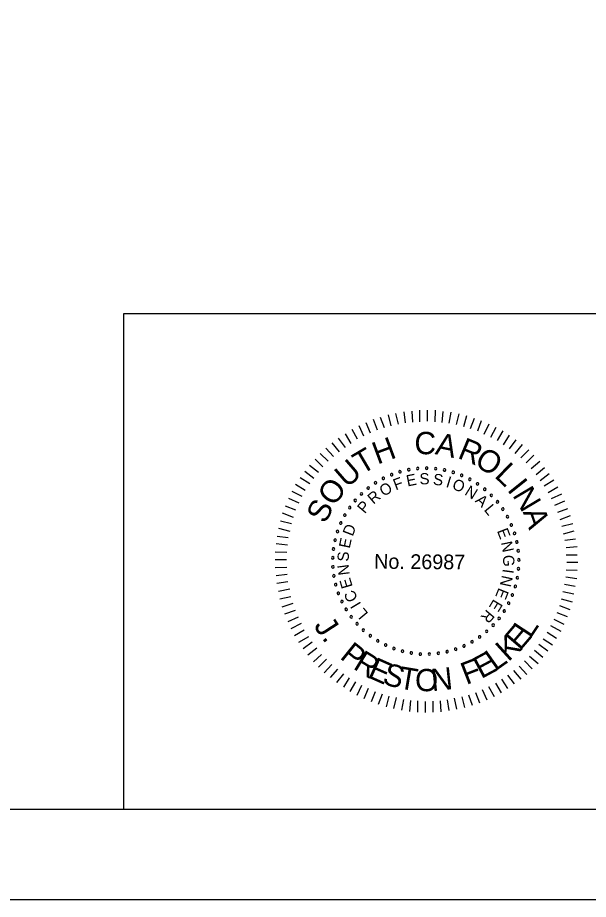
# Model space of a CAD drawing. Extents: x -305 to -161, y -187 to -99.
# Drawn here: x -216.99 to -204.34, y -187.49 to -167.93 of the extents above; entities that cross this region are included whole.
import ezdxf

# ---------------------------------------------------------------- set-up
doc = ezdxf.new("R2010")
doc.units = 0
for name, color, linetype in [('BR_BORDER LINES', 7, 'Continuous'), ('BR_TEXT', 7, 'Continuous'), ('Level 31', 7, 'Continuous')]:
    doc.layers.add(name, color=color, linetype=linetype)

msp = doc.modelspace()

# ---------------------------------------------------------------- linework, layer by layer
at = {"layer": 'BR_BORDER LINES'}
for p, q in [((-214.64, -174.489), (-193.18, -174.489)), ((-214.64, -185.489), (-214.64, -174.489)), ((-297.843, -185.489), (-163.178, -185.489))]:
    msp.add_line(p, q, dxfattribs=at)
at = {"layer": 'BR_TEXT'}
for p, q in [((-208.077, -176.892), (-208.075, -176.634)), ((-207.909, -176.883), (-207.907, -176.636)), ((-207.741, -176.895), (-207.732, -176.637)), ((-208.861, -177.026), (-208.949, -176.795)), ((-208.717, -176.986), (-208.77, -176.742)), ((-208.552, -176.946), (-208.608, -176.709)), ((-208.394, -176.917), (-208.429, -176.673)), ((-208.236, -176.901), (-208.251, -176.657)), ((-207.58, -176.906), (-207.561, -176.663)), ((-207.426, -176.925), (-207.382, -176.681)), ((-207.265, -176.957), (-207.208, -176.721)), ((-207.1, -176.999), (-207.036, -176.756)), ((-206.953, -177.042), (-206.865, -176.813)), ((-209.323, -177.211), (-209.427, -176.987)), ((-209.175, -177.144), (-209.269, -176.92)), ((-209.02, -177.076), (-209.103, -176.842)), ((-206.795, -177.095), (-206.708, -176.862)), ((-206.652, -177.165), (-206.54, -176.942)), ((-206.508, -177.234), (-206.383, -177.012)), ((-209.602, -177.377), (-209.724, -177.16)), ((-209.461, -177.282), (-209.582, -177.065)), ((-206.358, -177.308), (-206.229, -177.093)), ((-206.225, -177.405), (-206.089, -177.19)), ((-209.861, -177.564), (-210.021, -177.363)), ((-209.726, -177.462), (-209.883, -177.258)), ((-206.091, -177.492), (-205.946, -177.291)), ((-205.962, -177.596), (-205.799, -177.398)), ((-210.11, -177.771), (-210.287, -177.594)), ((-209.993, -177.662), (-210.159, -177.482)), ((-205.836, -177.696), (-205.663, -177.519)), ((-210.228, -177.894), (-210.402, -177.724)), ((-205.723, -177.807), (-205.55, -177.634)), ((-205.611, -177.932), (-205.421, -177.765)), ((-210.432, -178.153), (-210.63, -177.993)), ((-210.328, -178.02), (-210.526, -177.864)), ((-205.502, -178.06), (-205.316, -177.907)), ((-210.519, -178.269), (-210.735, -178.137)), ((-205.407, -178.194), (-205.21, -178.038)), ((-205.319, -178.312), (-205.109, -178.183)), ((-210.617, -178.416), (-210.832, -178.287)), ((-205.231, -178.46), (-205.017, -178.335)), ((-210.686, -178.552), (-210.912, -178.441)), ((-205.16, -178.598), (-204.929, -178.49)), ((-210.826, -178.853), (-211.059, -178.766)), ((-210.756, -178.699), (-210.985, -178.598)), ((-205.089, -178.746), (-204.862, -178.648)), ((-210.876, -179.014), (-211.122, -178.923)), ((-205.022, -178.901), (-204.795, -178.817)), ((-204.968, -179.063), (-204.738, -178.976)), ((-210.925, -179.158), (-211.168, -179.098)), ((-204.928, -179.207), (-204.688, -179.151)), ((-210.954, -179.326), (-211.204, -179.262)), ((-204.895, -179.376), (-204.654, -179.316)), ((-210.996, -179.47), (-211.24, -179.437)), ((-204.862, -179.52), (-204.625, -179.491)), ((-211.015, -179.634), (-211.261, -179.605)), ((-204.836, -179.685), (-204.592, -179.66)), ((-211.034, -179.957), (-211.285, -179.955)), ((-211.026, -179.792), (-211.284, -179.79)), ((-204.831, -179.843), (-204.59, -179.845)), ((-211.029, -180.129), (-211.286, -180.133)), ((-204.822, -180.008), (-204.578, -180.01)), ((-211.02, -180.283), (-211.267, -180.312)), ((-204.841, -180.334), (-204.598, -180.367)), ((-204.833, -180.18), (-204.593, -180.189)), ((-211.004, -180.448), (-211.248, -180.484)), ((-204.87, -180.499), (-204.634, -180.538)), ((-210.964, -180.606), (-211.215, -180.659)), ((-204.906, -180.656), (-204.666, -180.713)), ((-210.938, -180.775), (-211.182, -180.831)), ((-210.891, -180.923), (-211.139, -181.006)), ((-204.942, -180.824), (-204.702, -180.885)), ((-210.845, -181.077), (-211.079, -181.161)), ((-205.04, -181.125), (-204.814, -181.213)), ((-204.984, -180.971), (-204.755, -181.059)), ((-210.777, -181.226), (-211.008, -181.334)), ((-205.11, -181.272), (-204.884, -181.384)), ((-210.71, -181.37), (-210.937, -181.489)), ((-210.642, -181.519), (-210.859, -181.644)), ((-205.183, -181.416), (-204.954, -181.538)), ((-210.547, -181.667), (-210.765, -181.792)), ((-205.347, -181.71), (-205.139, -181.839)), ((-205.257, -181.563), (-205.045, -181.692)), ((-210.462, -181.784), (-210.663, -181.93)), ((-210.361, -181.919), (-210.561, -182.075)), ((-205.437, -181.826), (-205.243, -181.975)), ((-210.262, -182.054), (-210.439, -182.217)), ((-205.645, -182.092), (-205.458, -182.258)), ((-205.535, -181.959), (-205.351, -182.118)), ((-210.146, -182.158), (-210.326, -182.338)), ((-210.031, -182.279), (-210.2, -182.463)), ((-205.874, -182.313), (-205.704, -182.5)), ((-205.76, -182.194), (-205.589, -182.377)), ((-209.901, -182.383), (-210.064, -182.57)), ((-209.768, -182.487), (-209.928, -182.678)), ((-206.002, -182.415), (-205.842, -182.605)), ((-209.645, -182.574), (-209.77, -182.782)), ((-209.505, -182.664), (-209.63, -182.879)), ((-206.402, -182.69), (-206.277, -182.907)), ((-206.268, -182.602), (-206.135, -182.812)), ((-206.133, -182.517), (-205.99, -182.71)), ((-209.368, -182.744), (-209.477, -182.967)), ((-209.221, -182.814), (-209.319, -183.037)), ((-209.068, -182.884), (-209.155, -183.11)), ((-206.699, -182.835), (-206.591, -183.059)), ((-206.554, -182.768), (-206.432, -182.992)), ((-208.91, -182.933), (-209.001, -183.166)), ((-208.766, -182.983), (-208.823, -183.219)), ((-208.602, -183.011), (-208.662, -183.258)), ((-208.444, -183.057), (-208.484, -183.29)), ((-208.287, -183.076), (-208.306, -183.323)), ((-208.129, -183.087), (-208.131, -183.335)), ((-207.792, -183.09), (-207.787, -183.338)), ((-207.631, -183.081), (-207.616, -183.329)), ((-207.476, -183.065), (-207.437, -183.299)), ((-207.315, -183.022), (-207.262, -183.27)), ((-207.15, -182.996), (-207.09, -183.233)), ((-207.002, -182.949), (-206.918, -183.183)), ((-206.843, -182.902), (-206.759, -183.13)), ((-207.961, -183.099), (-207.963, -183.343))]:
    msp.add_line(p, q, dxfattribs=at)
for centre, start, end in [((-208.517, -178.003), 16.1422, 196.1422), ((-208.517, -178.003), 196.1422, 16.1422), ((-208.323, -177.957), 10.6038, 190.6038), ((-208.323, -177.957), 190.6038, 10.6038), ((-208.126, -177.93), 5.0653, 185.0653), ((-208.126, -177.93), 185.0653, 5.0653), ((-207.926, -177.923), 359.5268, 179.5268), ((-207.926, -177.923), 179.5268, 359.5268), ((-207.727, -177.934), 173.9884, 353.9884), ((-207.727, -177.934), 353.9884, 173.9884), ((-207.531, -177.965), 168.4499, 348.4499), ((-207.531, -177.965), 348.4499, 168.4499), ((-207.338, -178.015), 162.9114, 342.9114), ((-207.338, -178.015), 342.9114, 162.9114), ((-208.887, -178.149), 27.2191, 207.2191), ((-208.887, -178.149), 207.2191, 27.2191), ((-208.706, -178.067), 21.6807, 201.6807), ((-208.706, -178.067), 201.6807, 21.6807), ((-207.15, -178.083), 157.373, 337.373), ((-207.15, -178.083), 337.373, 157.373), ((-206.97, -178.169), 151.8345, 331.8345), ((-206.97, -178.169), 331.8345, 151.8345), ((-209.223, -178.364), 38.2961, 218.2961), ((-209.223, -178.364), 218.2961, 38.2961), ((-209.06, -178.248), 32.7576, 212.7576), ((-209.06, -178.248), 212.7576, 32.7576), ((-206.8, -178.272), 146.2961, 326.2961), ((-206.8, -178.272), 326.2961, 146.2961), ((-206.639, -178.39), 140.7576, 320.7576), ((-206.639, -178.39), 320.7576, 140.7576), ((-209.373, -178.495), 43.8345, 223.8345), ((-209.373, -178.495), 223.8345, 43.8345), ((-206.492, -178.524), 135.2191, 315.2191), ((-206.492, -178.524), 315.2191, 135.2191), ((-209.633, -178.796), 54.9114, 234.9114), ((-209.633, -178.796), 234.9114, 54.9114), ((-209.511, -178.639), 49.373, 229.373), ((-209.511, -178.639), 229.373, 49.373), ((-206.357, -178.671), 129.6807, 309.6807), ((-206.357, -178.671), 309.6807, 129.6807), ((-209.74, -178.964), 60.4499, 240.4499), ((-209.74, -178.964), 240.4499, 60.4499), ((-206.238, -178.831), 124.1422, 304.1422), ((-206.238, -178.831), 304.1422, 124.1422), ((-206.135, -179.001), 118.6038, 298.6038), ((-206.135, -179.001), 298.6038, 118.6038), ((-209.83, -179.142), 65.9884, 245.9884), ((-209.83, -179.142), 245.9884, 65.9884), ((-206.048, -179.181), 113.0653, 293.0653), ((-206.048, -179.181), 293.0653, 113.0653), ((-209.903, -179.328), 71.5268, 251.5268), ((-209.903, -179.328), 251.5268, 71.5268), ((-205.979, -179.368), 107.5268, 287.5268), ((-205.979, -179.368), 287.5268, 107.5268), ((-209.957, -179.52), 77.0653, 257.0653), ((-209.957, -179.52), 257.0653, 77.0653), ((-205.929, -179.561), 101.9884, 281.9884), ((-205.929, -179.561), 281.9884, 101.9884), ((-209.993, -179.716), 82.6038, 262.6038), ((-209.993, -179.716), 262.6038, 82.6038), ((-205.897, -179.758), 96.4499, 276.4499), ((-205.897, -179.758), 276.4499, 96.4499), ((-210.009, -179.914), 88.1422, 268.1422), ((-210.009, -179.914), 268.1422, 88.1422), ((-205.885, -179.957), 90.9114, 270.9114), ((-205.885, -179.957), 270.9114, 90.9114), ((-210.006, -180.114), 93.6807, 273.6807), ((-210.006, -180.114), 273.6807, 93.6807), ((-205.892, -180.156), 85.373, 265.373), ((-205.892, -180.156), 265.373, 85.373), ((-209.984, -180.312), 99.2191, 279.2191), ((-209.984, -180.312), 279.2191, 99.2191), ((-205.918, -180.353), 79.8345, 259.8345), ((-205.918, -180.353), 259.8345, 79.8345), ((-209.943, -180.507), 104.7576, 284.7576), ((-209.943, -180.507), 284.7576, 104.7576), ((-205.963, -180.548), 74.2961, 254.2961), ((-205.963, -180.548), 254.2961, 74.2961), ((-209.884, -180.697), 110.2961, 290.2961), ((-209.884, -180.697), 290.2961, 110.2961), ((-206.026, -180.737), 68.7576, 248.7576), ((-206.026, -180.737), 248.7576, 68.7576), ((-209.806, -180.881), 115.8345, 295.8345), ((-209.806, -180.881), 295.8345, 115.8345), ((-206.108, -180.918), 63.2191, 243.2191), ((-206.108, -180.918), 243.2191, 63.2191), ((-209.711, -181.056), 121.373, 301.373), ((-209.711, -181.056), 301.373, 121.373), ((-206.207, -181.092), 57.6807, 237.6807), ((-206.207, -181.092), 237.6807, 57.6807), ((-209.599, -181.221), 126.9114, 306.9114), ((-209.599, -181.221), 306.9114, 126.9114), ((-206.321, -181.255), 52.1422, 232.1422), ((-206.321, -181.255), 232.1422, 52.1422), ((-209.472, -181.375), 132.4499, 312.4499), ((-209.472, -181.375), 312.4499, 132.4499), ((-209.331, -181.515), 137.9884, 317.9884), ((-209.331, -181.515), 317.9884, 137.9884), ((-206.596, -181.543), 41.0653, 221.0653), ((-206.596, -181.543), 221.0653, 41.0653), ((-206.452, -181.406), 46.6038, 226.6038), ((-206.452, -181.406), 226.6038, 46.6038), ((-209.177, -181.642), 143.5268, 323.5268), ((-209.177, -181.642), 323.5268, 143.5268), ((-209.011, -181.753), 329.0653, 149.0653), ((-206.752, -181.667), 35.5268, 215.5268), ((-206.752, -181.667), 215.5268, 35.5268), ((-209.011, -181.753), 149.0653, 329.0653), ((-208.836, -181.847), 154.6038, 334.6038), ((-208.836, -181.847), 334.6038, 154.6038), ((-208.652, -181.924), 160.1422, 340.1422), ((-208.652, -181.924), 340.1422, 160.1422), ((-207.283, -181.938), 18.9114, 198.9114), ((-207.098, -181.865), 24.4499, 204.4499), ((-207.098, -181.865), 204.4499, 24.4499), ((-206.92, -181.774), 29.9884, 209.9884), ((-206.92, -181.774), 209.9884, 29.9884), ((-208.462, -181.983), 165.6807, 345.6807), ((-208.462, -181.983), 345.6807, 165.6807), ((-208.267, -182.023), 171.2191, 351.2191), ((-208.267, -182.023), 351.2191, 171.2191), ((-208.068, -182.045), 356.7576, 176.7576), ((-208.068, -182.045), 176.7576, 356.7576), ((-207.869, -182.047), 2.2961, 182.2961), ((-207.869, -182.047), 182.2961, 2.2961), ((-207.67, -182.029), 7.8345, 187.8345), ((-207.67, -182.029), 187.8345, 7.8345), ((-207.474, -181.993), 13.373, 193.373), ((-207.474, -181.993), 193.373, 13.373), ((-207.283, -181.938), 198.9114, 18.9114)]:
    msp.add_arc(centre, 0.028, start, end, dxfattribs=at)
at = {"layer": 'Level 31'}
msp.add_lwpolyline([(-305.176, -187.489), (-161.176, -187.489), (-161.176, -99.489), (-305.176, -99.489)], close=True, dxfattribs=at)

# ---------------------------------------------------------------- texts
at = {"layer": 'BR_TEXT'}
for s, height, rotation, p in [('C', 0.496, 359.5482, (-208.2, -177.612)), ('A', 0.496, 348.1981, (-207.755, -177.609)), ('H', 0.496, 20.3637, (-209.018, -177.846)), ('R', 0.496, 337.4344, (-207.262, -177.689)), ('T', 0.496, 30.4992, (-209.37, -178.076)), ('O', 0.496, 326.5869, (-206.893, -177.836)), ('U', 0.496, 40.8022, (-209.694, -178.375)), ('L', 0.496, 315.9488, (-206.442, -178.107)), ('O', 0.496, 52.0267, (-209.993, -178.79)), ('F', 0.249, 20.6127, (-208.613, -178.417)), ('E', 0.249, 11.4103, (-208.352, -178.33)), ('S', 0.249, 2.208, (-208.081, -178.286)), ('S', 0.249, 352.6608, (-207.796, -178.287)), ('I', 0.249, 343.1136, (-207.515, -178.335)), ('O', 0.249, 338.4392, (-207.381, -178.376)), ('I', 0.496, 308.6613, (-206.157, -178.404)), ('O', 0.249, 30.8477, (-208.882, -178.561)), ('N', 0.249, 328.2042, (-207.103, -178.501)), ('N', 0.496, 300.7037, (-206.035, -178.521)), ('R', 0.249, 40.3949, (-209.107, -178.737)), ('A', 0.249, 318.657, (-206.867, -178.662)), ('S', 0.496, 63.2511, (-210.174, -179.173)), ('P', 0.249, 49.9421, (-209.299, -178.947)), ('L', 0.249, 309.4546, (-206.668, -178.851)), ('A', 0.496, 289.4792, (-205.798, -178.894)), ('D', 0.249, 69.0364, (-209.567, -179.448)), ('E', 0.249, 291.049, (-206.372, -179.312)), ('E', 0.249, 78.2388, (-209.633, -179.715)), ('N', 0.249, 281.8466, (-206.283, -179.572)), ('S', 0.249, 87.786, (-209.656, -179.999)), ('No. 26987', 0.327, 359.5268, (-209.092, -180.153)), ('G', 0.249, 272.2995, (-206.237, -179.853)), ('N', 0.249, 97.3332, (-209.632, -180.283)), ('E', 0.249, 106.5355, (-209.564, -180.549)), ('N', 0.249, 257.7339, (-206.256, -180.287)), ('I', 0.249, 262.4084, (-206.238, -180.149)), ('C', 0.249, 116.4266, (-209.444, -180.819)), ('E', 0.249, 248.1867, (-206.328, -180.563)), ('I', 0.249, 121.1011, (-209.372, -180.939)), ('E', 0.249, 238.9844, (-206.44, -180.814)), ('L', 0.249, 129.9595, (-209.209, -181.147)), ('R', 0.249, 229.782, (-206.591, -181.044)), ('J', 0.494, 302.9559, (-210.441, -181.421)), ('E', 0.494, 49.3639, (-205.857, -181.989)), ('L', 0.494, 56.4247, (-205.627, -181.718)), ('.', 0.494, 309.3974, (-210.264, -181.693)), ('K', 0.494, 42.3031, (-206.118, -182.229)), ('P', 0.494, 321.1035, (-209.871, -182.13)), ('R', 0.494, 328.5359, (-209.578, -182.362)), ('E', 0.494, 28.1814, (-206.719, -182.605)), ('L', 0.494, 35.2422, (-206.407, -182.436)), ('E', 0.494, 335.9684, (-209.257, -182.555)), ('S', 0.494, 343.0292, (-208.932, -182.698)), ('F', 0.494, 21.1206, (-207.05, -182.735)), ('T', 0.494, 350.4617, (-208.573, -182.804)), ('O', 0.494, 358.1419, (-208.192, -182.863)), ('N', 0.494, 5.8221, (-207.805, -182.872))]:
    msp.add_text(s, height=height, rotation=rotation, dxfattribs=at).set_placement(p)

doc.saveas('drawing.dxf')
